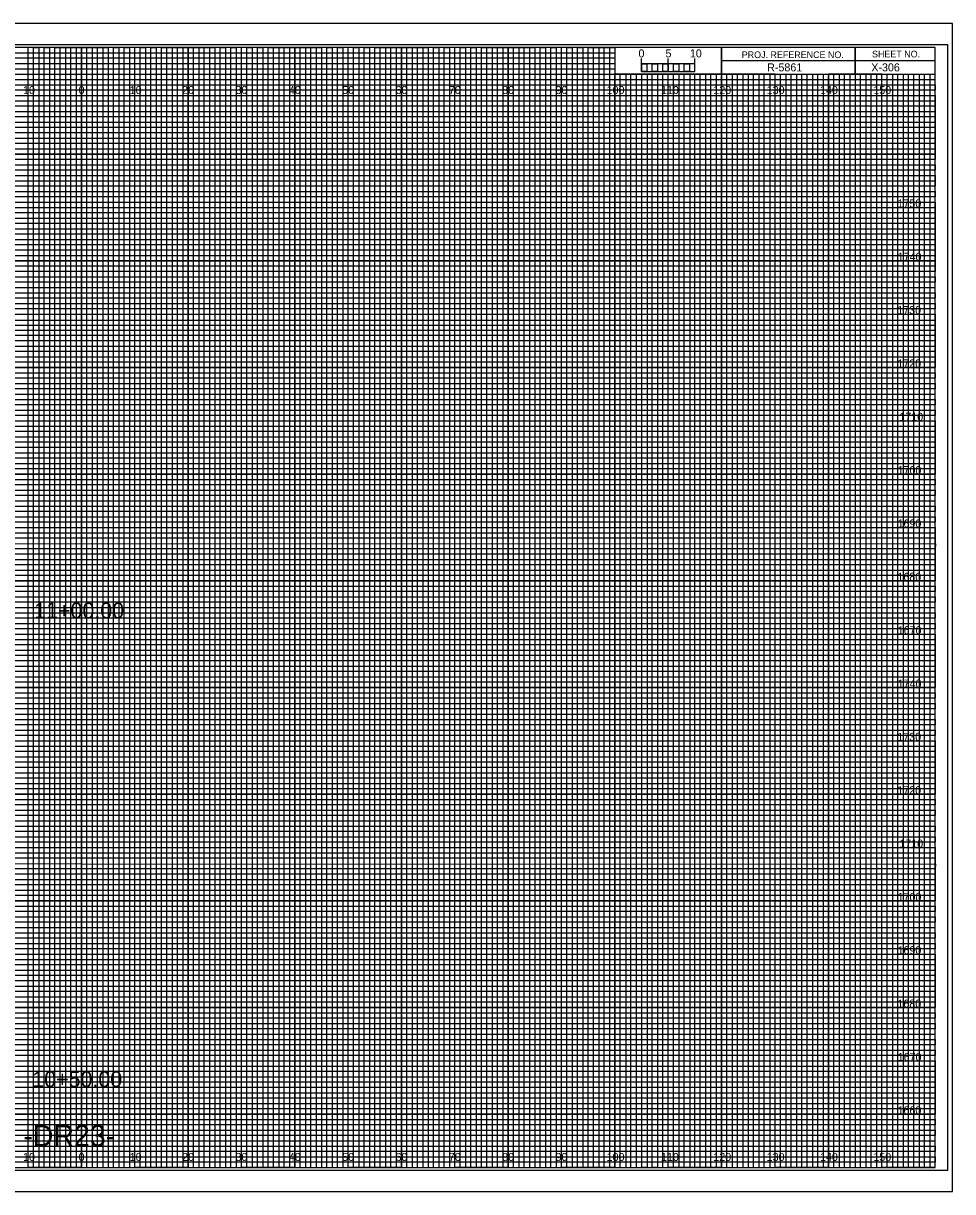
# Model space of a CAD drawing. Extents: x -13 to 323, y -5 to 215.
# Drawn here: x 149.1 to 323.3, y -4.5 to 214.5 of the extents above; entities that cross this region are included whole.
import ezdxf

# ---------------------------------------------------------------- set-up
doc = ezdxf.new("R2010")
doc.units = 0
for name, color, linetype in [('Prop Horizontal Alignment', 7, 'Continuous'), ('Prop XS Alignment Label', 7, 'Continuous'), ('Prop XS Bar Scale Labels', 7, 'Continuous'), ('Prop XS Project Number', 7, 'Continuous'), ('Prop XS Sheet Number', 7, 'Continuous'), ('Raster_Level_0', 7, 'Continuous'), ('Scratch_Level_3', 7, 'Continuous'), ('Sheet Cross Section CELL', 7, 'Continuous'), ('Sheet Cross Section Grid Major CELL', 7, 'Continuous'), ('Sheet Cross Section Grid Middle CELL', 7, 'Continuous'), ('Sheet Cross Section Grid Minor 1 CELL', 7, 'Continuous'), ('Sheet Cross Section Grid Minor 2 CELL', 7, 'Continuous'), ('Sheet Cross Section Scale CELL', 7, 'Continuous'), ('Sheet Cutting Line CELL', 7, 'Continuous'), ('Sheet DOT Grid CELL', 7, 'Continuous'), ('Sheet Plot Border Inside CELL', 7, 'Continuous'), ('Sheet Plot Border Outside CELL', 7, 'Continuous')]:
    doc.layers.add(name, color=color, linetype=linetype)

msp = doc.modelspace()

# ---------------------------------------------------------------- linework, layer by layer
at = {"layer": 'Sheet Cross Section CELL'}
for p, q in [((305, 210), (305, 205)), ((305, 205), (305, 210)), ((280, 207.5), (280, 205)), ((320, 207.49), (280, 207.49)), ((280, 205), (320, 205))]:
    msp.add_line(p, q, dxfattribs=at)
for points in [[(320, 210), (0, 210), (0, 0), (320, 0)], [(280, 210), (260, 210), (260, 205.03), (280, 205.03)], [(320, 210), (280, 210), (280, 205), (320, 205)]]:
    msp.add_lwpolyline(points, close=True, dxfattribs=at)
at = {"layer": 'Sheet Cross Section Grid Major CELL'}
for p, q in [((150, 210), (140, 210)), ((150, 0), (150, 210)), ((170, 210), (160, 210)), ((160, 210), (160, 0)), ((170, 0), (170, 210)), ((190, 210), (180, 210)), ((180, 210), (180, 0)), ((190, 0), (190, 210)), ((210, 210), (200, 210)), ((200, 210), (200, 0)), ((210, 0), (210, 210)), ((230, 210), (220, 210)), ((220, 210), (220, 0)), ((230, 0), (230, 210)), ((250, 210), (240, 210)), ((240, 210), (240, 0)), ((250, 0), (250, 210)), ((260, 210), (260, 0)), ((270, 0), (270, 205)), ((290, 205), (280, 205)), ((280, 205), (280, 0)), ((290, 0), (290, 205)), ((310, 205), (300, 205)), ((300, 205), (300, 0)), ((310, 0), (310, 205)), ((160, 0), (150, 0)), ((180, 0), (170, 0)), ((200, 0), (190, 0)), ((220, 0), (210, 0)), ((240, 0), (230, 0)), ((260, 0), (250, 0)), ((280, 0), (270, 0)), ((300, 0), (290, 0)), ((320, 0), (310, 0)), ((320, 0), (320, 0))]:
    msp.add_line(p, q, dxfattribs=at)
for points in [[(0, 200), (320, 200), (320, 190), (0, 190)], [(0, 180), (320, 180), (320, 170), (0, 170)], [(0, 160), (320, 160), (320, 150), (0, 150)], [(0, 140), (320, 140), (320, 130), (0, 130)], [(0, 120), (320, 120), (320, 110), (0, 110)], [(0, 100), (320, 100), (320, 90), (0, 90)], [(0, 80), (320, 80), (320, 70), (0, 70)], [(0, 60), (320, 60), (320, 50), (0, 50)], [(0, 40), (320, 40), (320, 30), (0, 30)], [(0, 20), (320, 20), (320, 10), (0, 10)]]:
    msp.add_lwpolyline(points, dxfattribs=at)
at = {"layer": 'Sheet Cross Section Grid Middle CELL'}
for points in [[(145, 0), (155, 0), (155, 210), (165, 210), (165, 0), (175, 0), (175, 210), (185, 210), (185, 0), (195, 0), (195, 210), (205, 210), (205, 0), (215, 0), (215, 210), (225, 210), (225, 0), (235, 0), (235, 210), (245, 210), (245, 0), (255, 0), (255, 210), (259.93, 210), (260, 210), (260, 205), (264.99, 205), (264.99, 0), (275, 0), (275, 205), (285, 205), (285, 0), (295, 0), (295, 205), (305, 205), (305, 0), (315, 0), (315, 205)], [(0, 205), (275, 205)], [(0, 185), (320, 185), (320, 195), (0, 195)], [(0, 165), (320, 165), (320, 175), (0, 175)], [(0, 145), (320, 145), (320, 155), (0, 155)], [(0, 125), (320, 125), (320, 135), (0, 135)], [(0, 105), (320, 105), (320, 115), (0, 115)], [(0, 85), (320, 85), (320, 95), (0, 95)], [(0, 65), (320, 65), (320, 75), (0, 75)], [(0, 45), (320, 45), (320, 55), (0, 55)], [(0, 25), (320, 25), (320, 35), (0, 35)], [(0, 5), (320, 5), (320, 15), (0, 15)]]:
    msp.add_lwpolyline(points, dxfattribs=at)
at = {"layer": 'Sheet Cross Section Grid Minor 1 CELL'}
for p, q in [((0, 209), (260, 209)), ((260, 209), (260, 207.98)), ((260, 207.98), (0, 207.98)), ((0, 207), (260, 207)), ((260, 205.89), (0, 205.89)), ((260, 207), (260, 205.89)), ((0, 204), (320, 204))]:
    msp.add_line(p, q, dxfattribs=at)
for points in [[(0, 203), (270, 203), (320, 203), (320, 202), (0, 202)], [(0, 201), (320, 201), (320, 199), (0, 199)], [(0, 198), (320, 198), (320, 197), (0, 196.98)], [(0, 196), (320, 196), (320, 194), (0, 194)], [(0, 193), (320, 193), (320, 192), (0, 192)], [(0, 191), (320, 191), (320, 189), (0, 189)], [(0, 188), (320, 188), (320, 187), (0, 187)], [(0, 186), (320, 186), (320, 184), (0, 184)], [(0, 183), (320, 183), (320, 182), (0, 182)], [(0, 181), (320, 181), (320, 179), (0, 179)], [(0, 178), (320, 178), (320, 177), (0, 177)], [(0, 176), (320, 176), (320, 173.95), (320, 173), (320, 172), (0, 172)], [(0, 174), (320, 174), (320, 173), (0, 173)], [(0, 171), (320, 171), (320, 169), (0, 169.03)], [(0, 169.03), (320, 169), (320, 168), (0, 168)], [(0, 167), (320, 167), (320, 166), (0, 166)], [(0, 164), (320, 164), (320, 163), (0, 163)], [(0, 162), (320, 162), (320, 161), (0, 161)], [(-0.07, 158.89), (320, 158.89), (320, 157.88), (-0.07, 157.88)], [(0, 157), (320, 157), (320, 156), (0, 156)], [(0, 154), (320, 154), (320, 153), (0, 153)], [(0, 152), (320, 152), (320, 151), (0, 151)], [(0, 149), (320, 149), (320, 148), (0, 148)], [(0, 147), (320, 147), (320, 146), (0, 146)], [(0, 144), (320, 144), (320, 143), (0, 143)], [(0, 142), (320, 142), (320, 141), (0, 141)], [(0, 139), (320, 139), (319.99, 137.98), (0, 138)], [(0, 137), (320, 137), (320, 136), (0, 136)], [(0, 134), (320, 134), (320, 133), (0, 133)], [(0, 132), (320, 132), (320, 131), (0, 131)], [(0, 129), (320, 129), (320, 128), (0, 128)], [(0, 127), (320, 127), (320, 126), (0, 126)], [(0, 124), (320, 124), (320, 123), (0, 123)], [(0, 122), (320, 122), (320, 121), (0, 121)], [(0, 119), (320, 119), (320, 118), (0, 118)], [(0, 116.99), (320.07, 116.91), (320, 116), (0, 116)], [(0, 114), (320, 114), (320, 113), (0, 113)], [(0, 112), (320, 112), (320, 111), (0, 111)], [(0, 109), (320, 109), (320, 108), (0, 108)], [(0, 107), (320, 107), (320, 106), (0, 106)], [(0, 104), (320, 104), (320, 103), (0, 103)], [(0, 102), (320, 102), (320, 101), (0, 101)], [(0, 99), (320, 99), (320, 98), (0, 98)], [(0, 97), (320, 97), (320, 96), (0, 96)], [(0, 94), (320, 94), (320, 93), (0, 93)], [(0, 92), (320, 92), (320, 91), (0, 91)], [(0, 89), (320, 89), (320, 88), (0, 88)], [(0, 87), (320, 87), (320, 86), (0, 86)], [(0, 84), (320, 84), (320, 83), (0, 83)], [(0, 82), (320, 82), (320, 81), (0, 81)], [(0, 79), (320, 79), (319.99, 77.98), (0, 78)], [(0, 77), (320, 77), (320, 76), (0, 76)], [(0, 74), (320, 74), (320, 73), (0, 73)], [(0, 72), (320, 72), (320, 71), (0, 71)], [(0, 69), (320, 69), (320, 68), (0, 68)], [(0, 67), (320, 67), (320, 66), (0, 66)], [(0, 64), (320, 64), (320, 63), (0, 63)], [(0, 62), (320, 62), (320, 61), (0, 61)], [(0, 59), (320, 59), (320, 58), (0, 58)], [(0, 56.99), (320.07, 56.91), (320, 56), (0, 56)], [(0, 54), (320, 54), (320, 53), (0, 53)], [(0, 52), (320, 52), (320, 51), (0, 51)], [(0, 49), (320, 49), (320, 48), (0, 48)], [(0, 47), (320, 47), (320, 46), (0, 46)], [(0, 44), (320, 44), (320, 43), (0, 43)], [(0, 42), (320, 42), (320, 41), (0, 41)], [(0, 39), (320, 39), (320, 38), (0, 38)], [(0, 37), (320, 37), (320, 36), (0, 36)], [(0, 34), (320, 34), (320, 33), (0, 33)], [(0, 32), (320, 32), (320, 31), (0, 31)], [(0, 29), (320, 29), (320, 28), (0, 28)], [(0, 27), (320, 27), (320, 26), (0, 26)], [(0, 24), (320, 24), (320, 23), (0, 23)], [(0, 22), (320, 22), (320, 21), (0, 21)], [(0, 19), (320, 19), (320, 18), (0, 18)], [(0, 17), (320, 17), (320, 16), (0, 16)], [(0, 14), (320, 14), (320, 13), (0, 13)], [(0, 12), (320, 12), (320, 11), (0, 11)], [(0, 9), (320, 9), (320, 8), (0, 8)], [(0, 7), (320, 7), (320, 6), (0, 6)], [(0, 4), (320, 4), (320, 3), (0, 3)], [(0, 2), (320, 2), (320, 1), (0, 1)]]:
    msp.add_lwpolyline(points, dxfattribs=at)
at = {"layer": 'Sheet Cross Section Grid Minor 2 CELL'}
for p, q in [((267, 205), (266.01, 205)), ((266.01, 205), (266.01, 0)), ((267, 0), (267, 205)), ((269, 205), (268, 205)), ((268, 205), (268, 0)), ((269, 0), (269, 205)), ((266.01, 0), (265, 0)), ((268, 0), (267, 0))]:
    msp.add_line(p, q, dxfattribs=at)
for points in [[(150, 0), (151, 0), (151, 210), (152, 210), (152, 0)], [(152, 0), (153, 0), (153, 210), (154, 210), (154, 0)], [(155, 0), (156, 0), (156, 210), (157, 210), (157, 0)], [(157, 0), (158, 0), (158, 210), (159, 210), (159, 0)], [(160, 0), (161, 0), (161, 210), (162, 210), (162, 0)], [(162, 0), (163, 0), (163, 210), (164, 210), (164, 0)], [(165, 0), (166, 0), (166, 210), (167, 210), (167, 0)], [(167, 0), (168, 0), (168, 210), (169, 210), (169, 0)], [(170, 0), (171, 0), (171, 210), (172, 210), (172, 0)], [(172, 0), (173, 0), (173, 210), (174, 210), (174, 0)], [(175, 0), (176, 0), (176, 210), (177, 210), (177, 0)], [(177, 0), (178, 0), (178, 210), (179, 210), (179, 0)], [(180, 0), (181, 0), (181, 210), (182, 210), (182, 0)], [(182, 0), (183, 0), (183, 210), (184, 210), (184, 0)], [(185, 0), (186, 0), (186, 210), (187, 210), (187, 0)], [(187, 0), (188, 0), (188, 210), (189, 210), (189, 0)], [(190, 0), (191, 0), (191, 210), (192, 210), (192, 0)], [(192, 0), (193, 0), (193, 210), (194, 210), (194, 0)], [(195, 0), (196, 0), (196, 210), (197, 210), (197, 0)], [(197, 0), (198, 0), (198, 210), (199, 210), (199, 0)], [(200, 0), (201, 0), (201, 210), (202, 210), (202, 0)], [(202, 0), (203, 0), (203, 210), (204, 210), (204, 0)], [(205, 0), (206, 0), (206, 210), (207, 210), (207, 0)], [(207, 0), (208, 0), (208, 210), (209, 210), (209, 0)], [(210, 0), (211, 0), (211, 210), (212, 210), (212, 0)], [(212, 0), (213, 0), (213, 210), (214, 210), (214, 0)], [(215, 0), (216, 0), (216, 210), (217, 210), (217, 0)], [(217, 0), (218, 0), (218, 210), (219, 210), (219, 0)], [(220, 0), (221, 0), (221, 210), (222, 210), (222, 0)], [(222, 0), (223, 0), (223, 210), (224, 210), (224, 0)], [(225, 0), (226, 0), (226, 210), (227, 210), (227, 0)], [(227, 0), (228, 0), (228, 210), (229, 210), (229, 0)], [(230, 0), (231, 0), (231, 210), (232, 210), (232, 0)], [(232, 0), (233, 0), (233, 210), (234, 210), (234, 0)], [(235, 0), (236, 0), (236, 210), (237, 210), (237, 0)], [(237, 0), (238, 0), (238, 210), (239, 210), (239, 0)], [(240, 0), (241, 0), (241, 210), (242, 210), (242, 0)], [(242, 0), (243, 0), (243, 210), (244, 210), (244, 0)], [(245, 0), (246, 0), (246, 210), (247, 210), (247, 0)], [(247, 0), (248, 0), (248, 210), (249, 210), (249, 0)], [(250, 0), (251, 0), (251, 210), (252, 210), (252, 0)], [(252, 0), (253, 0), (253, 210), (254, 210), (254, 0)], [(255, 0), (256, 0), (256, 210), (257, 210), (257, 0)], [(257, 0), (258, 0), (258, 210), (259, 210), (259, 0)], [(260, 0), (261, 0), (261, 205), (262.02, 205), (262.02, 0)], [(262, 0), (263, 0), (263, 205), (263.99, 205), (263.99, 0)], [(270, 0), (270.98, 0), (270.98, 205), (272, 205), (272, 0)], [(272, 0), (273, 0), (273, 205), (274.05, 205), (274.05, 0)], [(275, 0), (276, 0), (276, 205), (277, 205), (277, 0)], [(277, 0), (278, 0), (278, 205), (279, 205), (279, 0)], [(280, 0), (281, 0), (281, 205), (282, 205), (282, 0)], [(282, 0), (283, 0), (283, 205), (284, 205), (284, 0)], [(285, 0), (286, 0), (286, 205), (287, 205), (287, 0)], [(287, 0), (288, 0), (288, 205), (289, 205), (289, 0)], [(290, 0), (291, 0), (291, 205), (292, 205), (292, 0)], [(292, 0), (293, 0), (293, 205), (294, 205), (294, 0)], [(295, 0), (296, 0), (296, 205), (297, 205), (297, 0)], [(297, 0), (298, 0), (298, 205), (299, 205), (299, 0)], [(300, 0), (301, 0), (301, 205), (302, 205), (302, 0)], [(302, 0), (303, 0), (303, 205), (304, 205), (304, 0)], [(305, 0), (306, 0), (306, 205), (307, 205), (307, 0)], [(307, 0), (308, 0), (308, 205), (309, 205), (309, 0)], [(310, 0), (311, 0), (311, 205), (312, 205), (312, 0)], [(312, 0), (313, 0), (313, 205), (314, 205), (314, 0)], [(315, 0), (316, 0), (316, 205), (317, 205), (317, 0)], [(317, 0), (318, 0), (318, 205), (319, 205), (319, 0)]]:
    msp.add_lwpolyline(points, dxfattribs=at)
at = {"layer": 'Sheet Cross Section Scale CELL'}
for p, q in [((265, 205.49), (265, 207.9)), ((265, 206.9), (265, 207.9)), ((270, 205.49), (270, 207.9)), ((275, 205.49), (275, 207.9)), ((275, 206.9), (275, 207.9))]:
    msp.add_line(p, q, dxfattribs=at)
for points in [[(275, 206.9), (265, 206.9), (265, 205.49), (275, 205.49)], [(265, 206.9), (266, 206.9), (266, 205.49), (265, 205.49)], [(267, 206.9), (268, 206.9), (268, 205.49), (267, 205.49)], [(269, 206.9), (270, 206.9), (270, 205.49), (269, 205.49)], [(271, 206.9), (272, 206.9), (272, 205.49), (271, 205.49)], [(273, 206.9), (274, 206.9), (274, 205.49), (273, 205.49)]]:
    msp.add_lwpolyline(points, close=True, dxfattribs=at)
at = {"layer": 'Sheet Cutting Line CELL'}
for p, q in [((323.3, 214.5), (-13.4, 214.5)), ((-13.4, -4.5), (323.3, -4.5))]:
    msp.add_line(p, q, dxfattribs=at)
at = {"layer": 'Sheet DOT Grid CELL'}
for p, q in [((150, 0), (150, 210)), ((160, 0), (160, 210)), ((170, 0), (170, 210)), ((180, 0), (180, 210)), ((190, 0), (190, 210)), ((200, 0), (200, 210)), ((210, 0), (210, 210)), ((220, 0), (220, 210)), ((230, 0), (230, 210)), ((240, 0), (240, 210)), ((250, 0), (250, 210)), ((260, 0), (260, 204.69)), ((270, 0), (270, 204.69)), ((280, 0), (280, 204.69)), ((290, 0), (290, 204.69)), ((300, 0), (300, 204.69)), ((310, 0), (310, 204.69)), ((0, 200), (320, 200)), ((0, 190), (320, 190)), ((0, 180), (320, 180)), ((0, 170), (320, 170)), ((0, 160), (320, 160)), ((0, 150), (320, 150)), ((0, 140), (320, 140)), ((0, 130), (320, 130)), ((0, 120), (320, 120)), ((0, 110), (320, 110)), ((0, 100), (320, 100)), ((0, 90), (320, 90)), ((0, 80), (320, 80)), ((0, 70), (320, 70)), ((0, 60), (320, 60)), ((0, 50), (320, 50)), ((0, 40), (320, 40)), ((0, 30), (320, 30)), ((0, 20), (320, 20)), ((0, 10), (320, 10))]:
    msp.add_line(p, q, dxfattribs=at)
at = {"layer": 'Sheet Plot Border Inside CELL'}
msp.add_lwpolyline([(-10.8, -0.5), (322.4, -0.5), (322.4, 210.5), (-10.8, 210.5)], close=True, dxfattribs=at)
at = {"layer": 'Sheet Plot Border Outside CELL'}
msp.add_lwpolyline([(-13.4, -4.5), (323.3, -4.5), (323.3, 214.5), (-13.4, 214.5)], close=True, dxfattribs=at)

# ---------------------------------------------------------------- texts
at = {"layer": 'Prop Horizontal Alignment'}
for s, p in [('1750', (312.96, 180)), ('1740', (313, 170)), ('1730', (312.92, 160)), ('1720', (312.93, 150)), ('1710', (313.31, 140)), ('1700', (312.98, 130)), ('1690', (312.97, 120)), ('1680', (312.95, 110)), ('1670', (313, 100)), ('1740', (313, 90)), ('1730', (312.92, 80)), ('1720', (312.93, 70)), ('1710', (313.31, 60)), ('1700', (312.98, 50)), ('1690', (312.97, 40)), ('1680', (312.95, 30)), ('1670', (313, 20)), ('1660', (312.97, 10))]:
    msp.add_text(s, height=1.5, dxfattribs=at).set_placement(p)
at = {"layer": 'Prop XS Alignment Label'}
msp.add_text('-DR23-', height=4, dxfattribs=at).set_placement((149.08, 4))
at = {"layer": 'Prop XS Bar Scale Labels'}
for s, p in [('5', (269.47, 208.12)), ('10', (274.04, 208.12))]:
    msp.add_text(s, height=1.5, dxfattribs=at).set_placement(p)
at = {"layer": 'Prop XS Project Number'}
msp.add_text('R-5861', height=1.5, dxfattribs=at).set_placement((288.53, 205.5))
at = {"layer": 'Prop XS Sheet Number'}
msp.add_text('X-306', height=1.5, dxfattribs=at).set_placement((308.05, 205.5))
at = {"layer": 'Raster_Level_0'}
for s, p in [('10', (149.04, 201.25)), ('0', (159.45, 201.25)), ('0', (159.45, 201.25)), ('10', (169.04, 201.25)), ('20', (178.86, 201.25)), ('30', (188.86, 201.25)), ('40', (198.86, 201.25)), ('50', (208.86, 201.25)), ('60', (218.86, 201.25)), ('70', (228.86, 201.25)), ('80', (238.86, 201.25)), ('90', (248.86, 201.25)), ('100', (258.44, 201.25)), ('110', (268.62, 201.25)), ('120', (278.44, 201.25)), ('130', (288.44, 201.25)), ('140', (298.44, 201.25)), ('150', (308.44, 201.25)), ('10', (149.04, 1.25)), ('0', (159.45, 1.25)), ('0', (159.45, 1.25)), ('10', (169.04, 1.25)), ('20', (178.86, 1.25)), ('30', (188.86, 1.25)), ('40', (198.86, 1.25)), ('50', (208.86, 1.25)), ('60', (218.86, 1.25)), ('70', (228.86, 1.25)), ('80', (238.86, 1.25)), ('90', (248.86, 1.25)), ('100', (258.44, 1.25)), ('110', (268.62, 1.25)), ('120', (278.44, 1.25)), ('130', (288.44, 1.25)), ('140', (298.44, 1.25)), ('150', (308.44, 1.25))]:
    msp.add_text(s, height=1.5, dxfattribs=at).set_placement(p)
at = {"layer": 'Scratch_Level_3'}
for s, p in [('11+00.00', (151.13, 102.94)), ('10+50.00', (150.77, 15.08))]:
    msp.add_text(s, height=3, dxfattribs=at).set_placement(p)
at = {"layer": 'Sheet Cross Section CELL'}
for s, p in [('PROJ. REFERENCE NO.', (283.77, 207.99)), ('SHEET NO.', (308.19, 208.12))]:
    msp.add_text(s, height=1.25, dxfattribs=at).set_placement(p)
at = {"layer": 'Sheet Cross Section Scale CELL'}
msp.add_text('0', height=1.5, dxfattribs=at).set_placement((264.41, 208.12))

doc.saveas('drawing.dxf')
